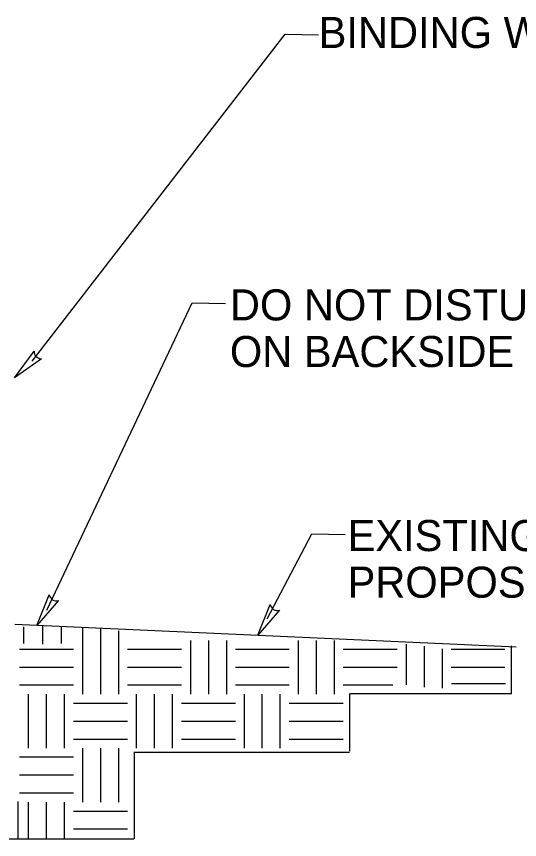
# Model space of a CAD drawing. Extents: x 0 to 2.83, y -0.06 to 1.83.
# Drawn here: x 2.2374 to 2.3788, y 0.3454 to 0.5771 of the extents above; entities that cross this region are included whole.
import ezdxf

# ---------------------------------------------------------------- set-up
doc = ezdxf.new("R2010")
doc.units = 0
for name, color, linetype in [('Edge_of_Truck_Apron', 7, 'Continuous'), ('Existing Grade', 7, 'Continuous'), ('Existing Soil', 7, 'Continuous'), ('Longitudinal Joint', 7, 'Continuous')]:
    doc.layers.add(name, color=color, linetype=linetype)

msp = doc.modelspace()

# ---------------------------------------------------------------- linework, layer by layer
at = {"layer": 'Edge_of_Truck_Apron'}
for p, q in [((2.241791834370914, 0.48004230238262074), (2.312946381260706, 0.5720784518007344)), ((2.312946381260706, 0.5720784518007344), (2.3223334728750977, 0.5718943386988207)), ((2.2458900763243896, 0.4100075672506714), (2.286777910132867, 0.4964450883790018)), ((2.286777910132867, 0.4964450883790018), (2.296165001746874, 0.49626097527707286)), ((2.2367933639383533, 0.47540932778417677), (2.242327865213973, 0.48290544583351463)), ((2.2367933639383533, 0.47540932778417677), (2.242327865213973, 0.48290544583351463)), ((2.2444598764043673, 0.4807052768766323), (2.2367933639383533, 0.47540932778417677)), ((2.2444598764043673, 0.4807052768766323), (2.2367933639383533, 0.47540932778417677)), ((2.307916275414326, 0.40750040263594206), (2.3204122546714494, 0.43145477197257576)), ((2.3204122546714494, 0.43145477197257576), (2.3297993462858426, 0.4312706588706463)), ((2.243082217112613, 0.40563658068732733), (2.2465657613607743, 0.41427876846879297)), ((2.243082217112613, 0.40563658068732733), (2.2465657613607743, 0.41427876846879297)), ((2.2491803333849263, 0.4126818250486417), (2.243082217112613, 0.40563658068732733)), ((2.2491803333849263, 0.4126818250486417), (2.243082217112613, 0.40563658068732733)), ((2.3052347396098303, 0.4029207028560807), (2.3087182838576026, 0.41156289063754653)), ((2.3052347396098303, 0.4029207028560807), (2.3087182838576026, 0.41156289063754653)), ((2.3113328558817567, 0.4099659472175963), (2.3052347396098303, 0.4029207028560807)), ((2.3113328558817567, 0.4099659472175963), (2.3052347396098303, 0.4029207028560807))]:
    msp.add_line(p, q, dxfattribs=at)
for centre, radius, start, end in [((2.244418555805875, 0.4827983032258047), 0.0020934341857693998, 177.06630020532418, 271.1309859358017), ((2.244418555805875, 0.4827983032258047), 0.0020934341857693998, 177.06630020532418, 271.1309859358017), ((2.2486167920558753, 0.4146979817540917), 0.0020934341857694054, 191.55166264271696, 285.61634837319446), ((2.2486167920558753, 0.4146979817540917), 0.0020934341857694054, 191.55166264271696, 285.61634837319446), ((2.310769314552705, 0.41198210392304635), 0.0020934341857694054, 191.55166264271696, 285.61634837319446), ((2.310769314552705, 0.41198210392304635), 0.0020934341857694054, 191.55166264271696, 285.61634837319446)]:
    msp.add_arc(centre, radius, start, end, dxfattribs=at)
at = {"layer": 'Existing Grade'}
msp.add_line((2.2368837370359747, 0.406065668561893), (2.3779310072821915, 0.39968482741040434), dxfattribs=at)
at = {"layer": 'Existing Soil'}
for p, q in [((2.2447249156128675, 0.4055772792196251), (2.2447249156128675, 0.4004024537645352)), ((2.2447249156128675, 0.4055772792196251), (2.2447249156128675, 0.4004024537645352)), ((2.239348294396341, 0.40528652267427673), (2.239348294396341, 0.400547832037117)), ((2.239348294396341, 0.40528652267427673), (2.239348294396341, 0.400547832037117)), ((2.249956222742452, 0.40514114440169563), (2.249956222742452, 0.400547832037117)), ((2.249956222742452, 0.40514114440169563), (2.249956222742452, 0.400547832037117)), ((2.2559641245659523, 0.4049091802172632), (2.2559641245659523, 0.38628790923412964)), ((2.2559641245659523, 0.4049091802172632), (2.2559641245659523, 0.38628790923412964)), ((2.2610192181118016, 0.40476380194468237), (2.2610192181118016, 0.38628790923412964)), ((2.2610192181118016, 0.40476380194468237), (2.2610192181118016, 0.38628790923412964)), ((2.266074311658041, 0.4041822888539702), (2.266074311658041, 0.38628790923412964)), ((2.266074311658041, 0.4041822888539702), (2.266074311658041, 0.38628790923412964)), ((2.2862946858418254, 0.40145318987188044), (2.2862946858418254, 0.38628790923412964)), ((2.2862946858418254, 0.40145318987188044), (2.2862946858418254, 0.38628790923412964)), ((2.2913497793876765, 0.40145318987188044), (2.2913497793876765, 0.38628790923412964)), ((2.2913497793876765, 0.40145318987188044), (2.2913497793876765, 0.38628790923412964)), ((2.2964048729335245, 0.40145318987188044), (2.2964048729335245, 0.38628790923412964)), ((2.2964048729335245, 0.40145318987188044), (2.2964048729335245, 0.38628790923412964)), ((2.3166252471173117, 0.40145318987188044), (2.3166252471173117, 0.38628790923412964)), ((2.3166252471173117, 0.40145318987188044), (2.3166252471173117, 0.38628790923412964)), ((2.3216803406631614, 0.40145318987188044), (2.3216803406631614, 0.38628790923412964)), ((2.3216803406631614, 0.40145318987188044), (2.3216803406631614, 0.38628790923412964)), ((2.326735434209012, 0.40145318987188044), (2.326735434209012, 0.38628790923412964)), ((2.326735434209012, 0.40145318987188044), (2.326735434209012, 0.38628790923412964)), ((2.25343657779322, 0.3989256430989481), (2.238271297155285, 0.3989256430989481)), ((2.25343657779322, 0.3989256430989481), (2.238271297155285, 0.3989256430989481)), ((2.283767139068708, 0.3989256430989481), (2.26860185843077, 0.3989256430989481)), ((2.283767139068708, 0.3989256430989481), (2.26860185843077, 0.3989256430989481)), ((2.3140977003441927, 0.3989256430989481), (2.2989324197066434, 0.3989256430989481)), ((2.3140977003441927, 0.3989256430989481), (2.2989324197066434, 0.3989256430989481)), ((2.3444282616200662, 0.3989256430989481), (2.329262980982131, 0.3989256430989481)), ((2.3444282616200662, 0.3989256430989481), (2.329262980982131, 0.3989256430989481)), ((2.3469558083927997, 0.4004024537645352), (2.3469558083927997, 0.39315528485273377)), ((2.3469558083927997, 0.4004024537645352), (2.3469558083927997, 0.38898045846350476)), ((2.352010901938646, 0.3998209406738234), (2.352010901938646, 0.39315528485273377)), ((2.352010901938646, 0.3998209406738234), (2.352010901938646, 0.38832316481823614)), ((2.357065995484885, 0.3990940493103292), (2.357065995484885, 0.39315528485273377)), ((2.357065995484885, 0.3990940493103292), (2.357065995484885, 0.3880310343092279)), ((2.374758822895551, 0.3989256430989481), (2.3595935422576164, 0.3989256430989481)), ((2.374758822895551, 0.3989256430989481), (2.3595935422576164, 0.3989256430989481)), ((2.3764786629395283, 0.3999353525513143), (2.3764786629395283, 0.38645193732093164)), ((2.25343657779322, 0.39387054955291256), (2.238271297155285, 0.39387054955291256)), ((2.25343657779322, 0.39387054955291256), (2.238271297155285, 0.39387054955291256)), ((2.283767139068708, 0.39387054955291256), (2.26860185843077, 0.39387054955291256)), ((2.283767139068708, 0.39387054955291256), (2.26860185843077, 0.39387054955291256)), ((2.3140977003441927, 0.39387054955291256), (2.2989324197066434, 0.39387054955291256)), ((2.3140977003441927, 0.39387054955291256), (2.2989324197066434, 0.39387054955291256)), ((2.3444282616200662, 0.39387054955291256), (2.329262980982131, 0.39387054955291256)), ((2.3444282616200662, 0.39387054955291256), (2.329262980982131, 0.39387054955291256)), ((2.374758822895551, 0.39387054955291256), (2.3595935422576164, 0.39387054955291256)), ((2.374758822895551, 0.39387054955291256), (2.3595935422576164, 0.39387054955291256)), ((2.3749048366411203, 0.389272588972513), (2.359739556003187, 0.389272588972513)), ((2.25343657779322, 0.38881545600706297), (2.238271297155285, 0.38881545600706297)), ((2.25343657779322, 0.38881545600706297), (2.238271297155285, 0.38881545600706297)), ((2.283767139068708, 0.38881545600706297), (2.26860185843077, 0.38881545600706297)), ((2.283767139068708, 0.38881545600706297), (2.26860185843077, 0.38881545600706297)), ((2.3140977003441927, 0.38881545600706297), (2.2989324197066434, 0.38881545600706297)), ((2.3140977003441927, 0.38881545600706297), (2.2989324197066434, 0.38881545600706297)), ((2.3432478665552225, 0.38881545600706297), (2.329262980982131, 0.38881545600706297)), ((2.3432478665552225, 0.38881545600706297), (2.329262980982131, 0.38881545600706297)), ((2.2407988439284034, 0.37112262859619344), (2.2407988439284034, 0.38628790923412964)), ((2.2407988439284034, 0.37112262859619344), (2.2407988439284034, 0.38628790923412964)), ((2.2458539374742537, 0.37112262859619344), (2.2458539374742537, 0.38628790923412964)), ((2.2458539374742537, 0.37112262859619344), (2.2458539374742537, 0.38628790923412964)), ((2.2509090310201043, 0.37112262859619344), (2.2509090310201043, 0.38628790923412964)), ((2.2509090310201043, 0.37112262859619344), (2.2509090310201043, 0.38628790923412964)), ((2.271129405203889, 0.37112262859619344), (2.271129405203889, 0.38628790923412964)), ((2.271129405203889, 0.37112262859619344), (2.271129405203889, 0.38628790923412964)), ((2.276184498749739, 0.37112262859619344), (2.276184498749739, 0.38628790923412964)), ((2.276184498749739, 0.37112262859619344), (2.276184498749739, 0.38628790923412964)), ((2.2812395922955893, 0.37112262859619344), (2.2812395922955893, 0.38628790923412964)), ((2.2812395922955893, 0.37112262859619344), (2.2812395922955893, 0.38628790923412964)), ((2.301459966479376, 0.37112262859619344), (2.301459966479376, 0.38628790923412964)), ((2.301459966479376, 0.37112262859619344), (2.301459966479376, 0.38628790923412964)), ((2.3065150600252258, 0.37112262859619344), (2.3065150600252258, 0.38628790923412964)), ((2.3065150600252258, 0.37112262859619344), (2.3065150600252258, 0.38628790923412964)), ((2.3115701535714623, 0.37112262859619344), (2.3115701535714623, 0.38628790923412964)), ((2.3115701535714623, 0.37112262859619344), (2.3115701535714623, 0.38628790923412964)), ((2.331011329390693, 0.38646086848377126), (2.331011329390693, 0.3702386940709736)), ((2.3312907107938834, 0.3864973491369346), (2.3765516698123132, 0.3864973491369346)), ((2.25343657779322, 0.3837603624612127), (2.26860185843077, 0.3837603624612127)), ((2.25343657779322, 0.3837603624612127), (2.26860185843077, 0.3837603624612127)), ((2.283767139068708, 0.3837603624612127), (2.2989324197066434, 0.3837603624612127)), ((2.283767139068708, 0.3837603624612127), (2.2989324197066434, 0.3837603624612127)), ((2.3140977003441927, 0.3837603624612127), (2.329262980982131, 0.3837603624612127)), ((2.3140977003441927, 0.3837603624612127), (2.329262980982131, 0.3837603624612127)), ((2.25343657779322, 0.37870526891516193), (2.26860185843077, 0.37870526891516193)), ((2.25343657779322, 0.37870526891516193), (2.26860185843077, 0.37870526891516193)), ((2.283767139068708, 0.37870526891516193), (2.2989324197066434, 0.37870526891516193)), ((2.283767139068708, 0.37870526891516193), (2.2989324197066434, 0.37870526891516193)), ((2.3140977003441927, 0.37870526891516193), (2.329262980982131, 0.37870526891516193)), ((2.3140977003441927, 0.37870526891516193), (2.329262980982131, 0.37870526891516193)), ((2.25343657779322, 0.3736501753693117), (2.26860185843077, 0.3736501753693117)), ((2.25343657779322, 0.3736501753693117), (2.26860185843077, 0.3736501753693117)), ((2.283767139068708, 0.3736501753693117), (2.2989324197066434, 0.3736501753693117)), ((2.283767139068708, 0.3736501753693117), (2.2989324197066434, 0.3736501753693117)), ((2.3140977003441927, 0.3736501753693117), (2.329262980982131, 0.3736501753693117)), ((2.3140977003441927, 0.3736501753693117), (2.329262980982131, 0.3736501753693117)), ((2.2559641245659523, 0.37112262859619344), (2.2559641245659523, 0.3559573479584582)), ((2.2559641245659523, 0.37112262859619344), (2.2559641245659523, 0.3559573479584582)), ((2.2610192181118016, 0.37112262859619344), (2.2610192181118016, 0.3559573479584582)), ((2.2610192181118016, 0.37112262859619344), (2.2610192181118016, 0.3559573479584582)), ((2.266074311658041, 0.37112262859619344), (2.266074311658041, 0.3559573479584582)), ((2.266074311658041, 0.37112262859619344), (2.266074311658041, 0.3559573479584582)), ((2.25343657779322, 0.36859508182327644), (2.238271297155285, 0.36859508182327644)), ((2.25343657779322, 0.36859508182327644), (2.238271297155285, 0.36859508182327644)), ((2.270475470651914, 0.3700732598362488), (2.270475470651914, 0.3456415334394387)), ((2.2704759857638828, 0.3700266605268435), (2.331036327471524, 0.3700266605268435)), ((2.25343657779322, 0.36353998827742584), (2.238271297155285, 0.36353998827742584)), ((2.25343657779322, 0.36353998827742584), (2.238271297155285, 0.36353998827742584)), ((2.25343657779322, 0.3584848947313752), (2.238271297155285, 0.3584848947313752)), ((2.25343657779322, 0.3584848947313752), (2.238271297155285, 0.3584848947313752)), ((2.237823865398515, 0.3455663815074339), (2.237823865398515, 0.35612727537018)), ((2.237823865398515, 0.3455663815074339), (2.237823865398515, 0.35612727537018)), ((2.2407988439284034, 0.34539645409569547), (2.2407988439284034, 0.3559573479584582)), ((2.2407988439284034, 0.34539645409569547), (2.2407988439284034, 0.3559573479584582)), ((2.2458539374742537, 0.34539645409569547), (2.2458539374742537, 0.3559573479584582)), ((2.2458539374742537, 0.34539645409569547), (2.2458539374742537, 0.3559573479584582)), ((2.2509090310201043, 0.34539645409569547), (2.2509090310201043, 0.3559573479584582)), ((2.2509090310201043, 0.34539645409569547), (2.2509090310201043, 0.3559573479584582)), ((2.25343657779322, 0.3534298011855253), (2.26860185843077, 0.3534298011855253)), ((2.25343657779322, 0.3534298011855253), (2.26860185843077, 0.3534298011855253)), ((2.25343657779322, 0.34837470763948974), (2.26860185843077, 0.34837470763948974)), ((2.25343657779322, 0.34837470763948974), (2.26860185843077, 0.34837470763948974)), ((2.00005332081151, 0.34559061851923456), (2.2703775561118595, 0.34559061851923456))]:
    msp.add_line(p, q, dxfattribs=at)
at = {"layer": 'Longitudinal Joint'}
for p, q in [((2.2458900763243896, 0.4100075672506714), (2.286777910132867, 0.4964450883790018)), ((2.286777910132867, 0.4964450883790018), (2.296165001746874, 0.49626097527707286)), ((2.307916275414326, 0.40750040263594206), (2.3204122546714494, 0.43145477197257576)), ((2.3204122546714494, 0.43145477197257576), (2.3297993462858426, 0.4312706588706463)), ((2.2368837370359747, 0.406065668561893), (2.3779310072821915, 0.39968482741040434))]:
    msp.add_line(p, q, dxfattribs=at)

# ---------------------------------------------------------------- texts
at = {"layer": 'Edge_of_Truck_Apron'}
for s, p in [('BINDING WIRE OR TWINE', (2.3223677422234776, 0.5682200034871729)), ('DO NOT DISTURB GROUND', (2.2973980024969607, 0.4915328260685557)), ('ON BACKSIDE OF THE BALE', (2.2973980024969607, 0.4784078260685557)), ('EXISTING OR ', (2.3304892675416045, 0.4265977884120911)), ('PROPOSED GRADE', (2.3304892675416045, 0.4134727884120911))]:
    msp.add_text(s, height=0.008749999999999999, dxfattribs=at).set_placement(p)

doc.saveas('drawing.dxf')
